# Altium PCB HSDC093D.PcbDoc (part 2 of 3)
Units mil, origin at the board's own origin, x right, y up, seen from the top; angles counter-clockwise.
Board outline 4360 x 2202.42 mil, 6 copper layers (Top Layer, GND1, VCC1, VCC2, GND2, Bottom Layer), stack 84.434 mil thick; 280 components, 182 nets, 800 pads, 401 vias.
Unrouted connection lines stored in the file: 5.
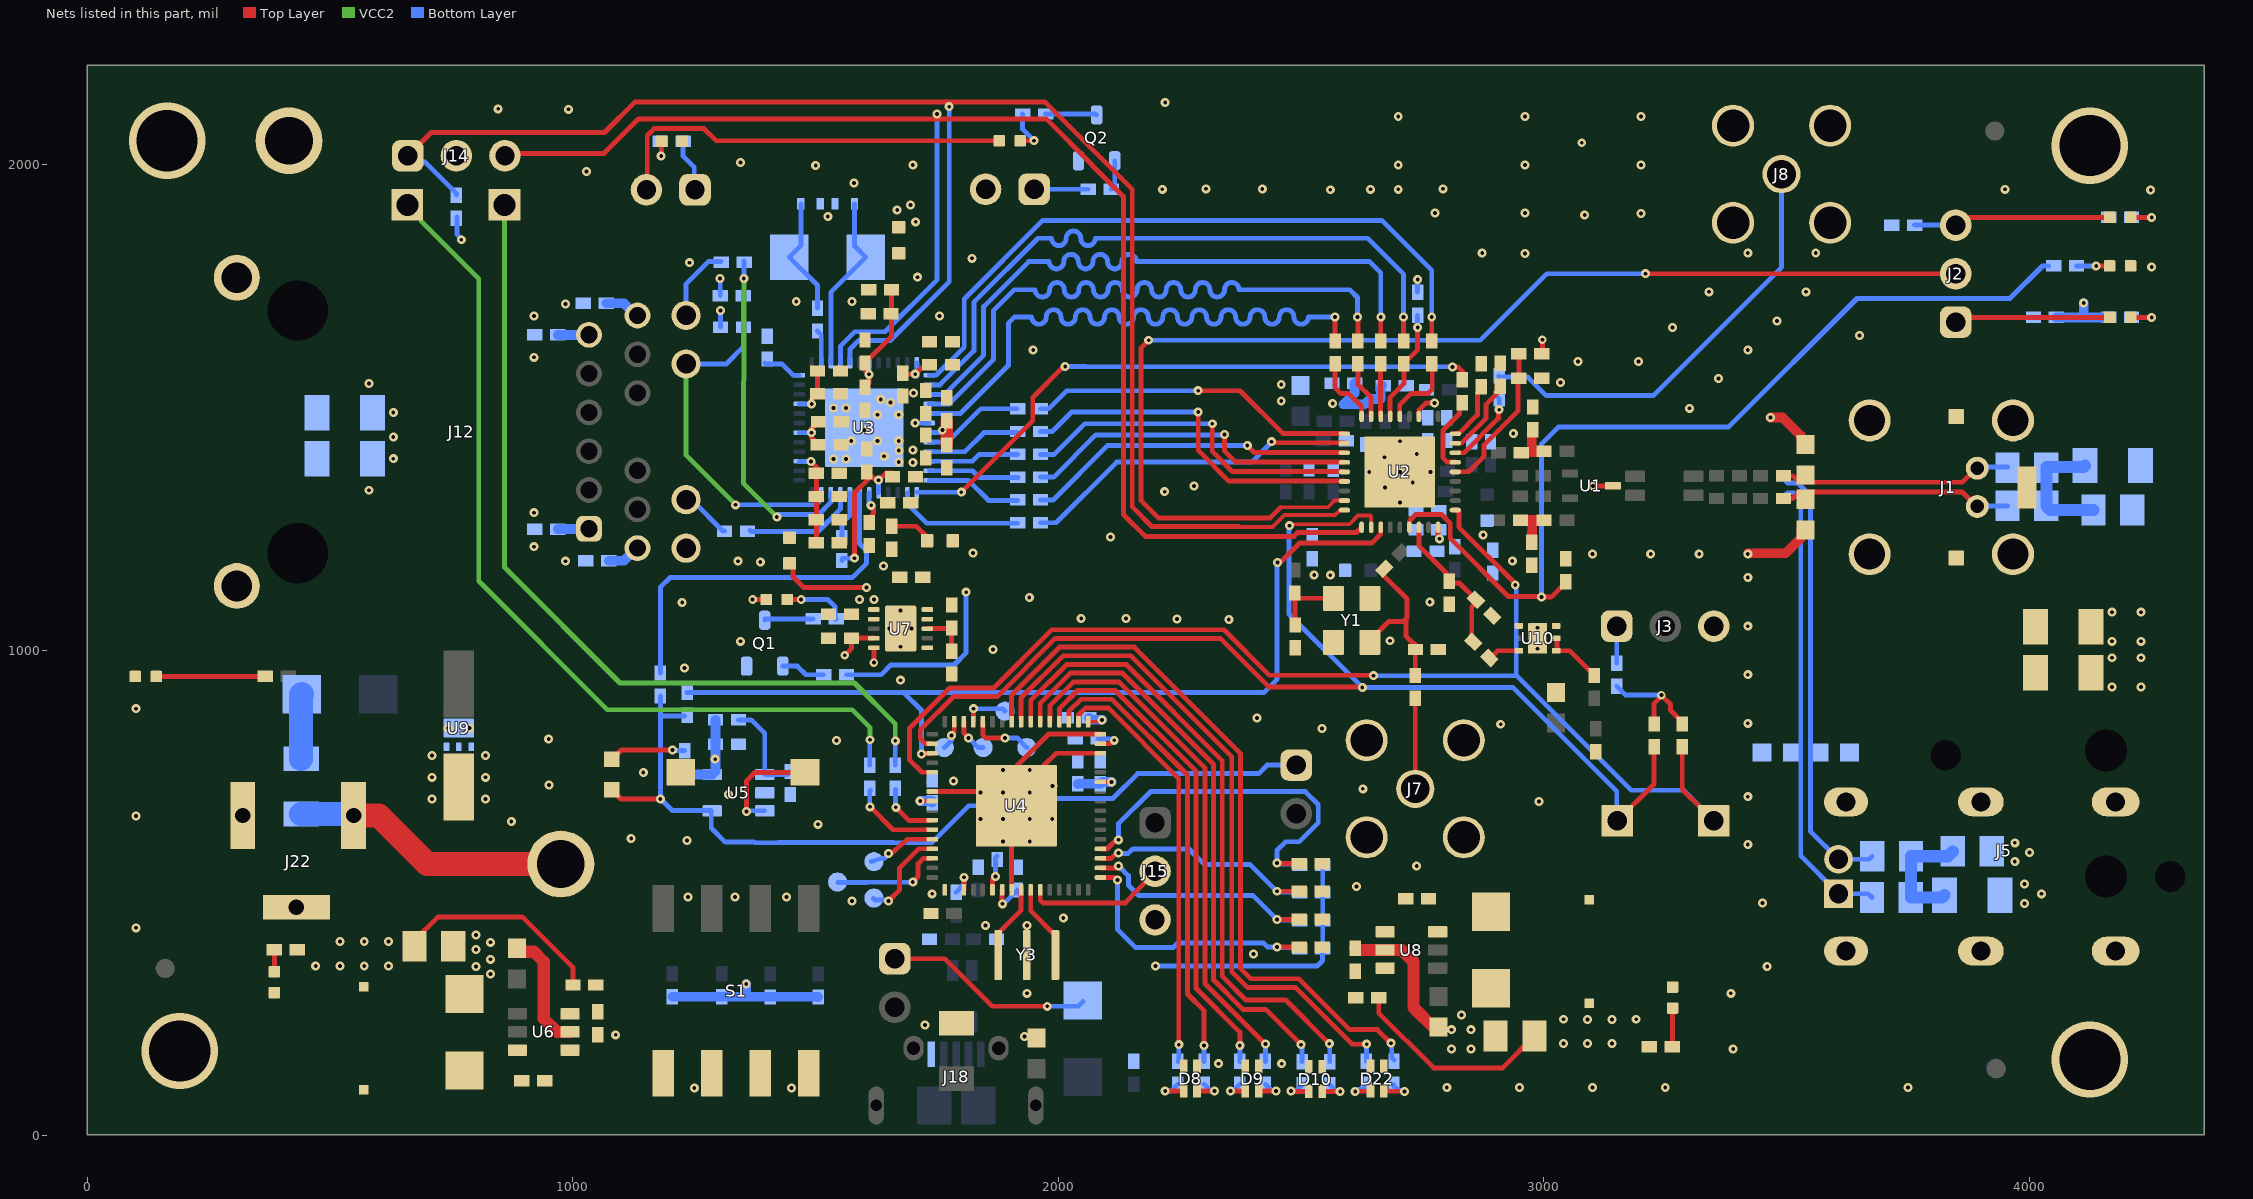
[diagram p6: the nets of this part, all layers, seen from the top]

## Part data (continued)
L1: library part CMP-0090833-1, "100μH @ 100kHz 2 Line Common Mode Choke Surface Mount 100mA DCR 3.12Ω", Manufacturer=Murata, Mouser Part Number=81-DLW32MH101XT2L, Operating Temperature Range="-40°C to +125°C", Test Frequency=100kHz, Tolerance_%=-25/+50%
L2: library part CMP-0003348-2, "Ferrite Bead, 1000 ohm @ 100 MHz, 0.6 A, 0603", Manufacturer=MuRata, Supplier Part Number 1=490-5215-1-ND, Value1="0.35 ohm", Value2=0.6A, ValueDisplayed="1000 ohm"
L3 L4 L5 L6 L7: library part CMP-0089848-1, "600 Ohms @ 100MHz 1 Power Line Ferrite Bead 0603 (1608 Metric) 1.3A 150mOhm", Digikey Part Number=490-13259-1-ND, Impedance At Frequency="600Ω @ 100MHz", Manufacturer=Murata, Mouser Part Number=81-BLM18KG601SH1D, Operating Temperature Range="-55°C to +125°C", Test Frequency=100MHz, Tolerance_%=25%
L8: library part CMP-0013079-2, "Coupled inductor,  A, 0.3 ohm, SMD", Manufacturer="Wurth Elektronik", Supplier Part Number 1=732-1469-1-ND
L9 L10: library part CMP-0064420-2, "Inductor, Shielded Drum Core, Ferrite, 15 uH, 1.15 A, 0.07 ohm, SMD", Manufacturer="Wurth Elektronik", Supplier Part Number 1=732-1045-1-ND, Value1="0.07 ohm", Value2=1.15A, ValueDisplayed=15uH
Logo1: library part CMP-0074844-1
Logo2: library part CMP-0074847-1, "FCC_disclaimer"
Logo3: library part CMP-0074838-1, "Texas Instrument Corporate Signature"
Logo4: library part CMP-0074769-1
Q1 Q2: library part CMP-0000376-2, "Transistor, NPN, 45 V, 0.1 A, SOT-23", Manufacturer="ON Semiconductor", Supplier Part Number 1=BC847CLT1GOSCT-ND, Value1="0.1 A", Value2=800
R1 R5 R16 R33 R95: library part CMP-0026237-2, "RES, 2.49 k, 1%, 0.063 W, AEC-Q200 Grade 0, 0402", Manufacturer=Vishay-Dale, Power_W=63mW, Supplier Part Number 1=541-2.49KLCT-ND, TempCo="100 ppm/C", Tolerance_%=1%, Value2=0.063W, Value_Code=2k49, ValueDisplayed=2.49k
R2 R13: library part CMP-0026210-2, "RES, 26.7, 1%, 0.063 W, AEC-Q200 Grade 0, 0402", Manufacturer=Vishay-Dale, Power_W=63mW, Supplier Part Number 1=541-26.7LCT-ND, TempCo="100 ppm/C", Tolerance_%=1%, Value2=0.063W, Value_Code=26R7, ValueDisplayed=26.7
R3 R7 R12 R20 R30 R61 R62 R65 R66 R67 R69 R101 R102: library part CMP-0026890-5, "RES, 2.2 k, 5%, 0.063 W, AEC-Q200 Grade 0, 0402", Manufacturer=Vishay-Dale, Power_W=63mW, Supplier Part Number 1=541-2.2KJCT-ND, TempCo="200 ppm/C", Tolerance_%=5%, Value2=0.063W, Value_Code=2k20, ValueDisplayed=2.2k
R4 R6 R8 R9 R10 R11 R17 R19 R22 R38 R56 R58 R59 R90 R91 R92 R93 R96 R98 R100: library part CMP-0081856-1, "RES, 0, 0%, 0.2 W, AEC-Q200 Grade 0, 0402", Manufacturer=Vishay-Dale, Power_W=200mW, Supplier Part Number 1=541-0.0YBTR-ND, Tolerance_%=0%, Value2=0.2W, Value_Code=0
R14 R15 R23 R24: library part CMP-0021848-2, "RES, 1.00 k, 1%, 0.25 W, 0805", Manufacturer=Panasonic, Power_W=250mW, Supplier Part Number 1=P16058CT-ND, TempCo="100 ppm/C", Tolerance_%=1%, Value2=0.25W, Value_Code=1k00, ValueDisplayed=1.00k
R18 R25: library part CMP-0020834-3, "RES, 100 k, 1%, 0.125 W, AEC-Q200 Grade 0, 0805", Manufacturer=Vishay-Dale, PartNumber=CRCW0805100KFKEA, Power_W=125mW, Supplier Part Number 1=541-100KCCT-ND, TempCo="100 ppm/C", Tolerance_%=1%, Value2=0.125W, Value_Code=100k
R21 R35: library part CMP-0018610-3, "RES, 1.0 M, 5%, 0.25 W, AEC-Q200 Grade 0, 1206", Manufacturer=Vishay-Dale, Power_W=250mW, Supplier Part Number 1=541-1.0MECT-ND, TempCo="200 ppm/C", Tolerance_%=5%, Value2=0.25W, Value_Code=1M00, ValueDisplayed=1.0M
R26 R31 R103 R104: library part CMP-0026992-3, "RES, 0, 5%, 0.1 W, AEC-Q200 Grade 0, 0402", Manufacturer=Panasonic, Power_W=100mW, Supplier Part Number 1=P0.0JCT-ND, TempCo="600 ppm/C", Tolerance_%=5%, Value2=0.1W, Value_Code=0000, ValueDisplayed=0
R27 R32 R34 R39 R40 R41 R42 R43 R44 R55 R72 R99: library part CMP-0026736-1, "RES, 470, 1%, 0.063 W, 0402", Manufacturer="Yageo America", Power_W=63mW, Supplier Part Number 1=311-470LRCT-ND, TempCo="100 ppm/C", Tolerance_%=1%, Value2=0.063W, Value_Code=470R, ValueDisplayed=470
R28: library part CMP-0026071-3, "RES, 1.00 k, 1%, 0.063 W, AEC-Q200 Grade 0, 0402", Manufacturer=Vishay-Dale, Power_W=63mW, Supplier Part Number 1=541-1.00KLCT-ND, TempCo="100 ppm/C", Tolerance_%=1%, Value2=0.063W, Value_Code=1k00, ValueDisplayed=1.00k
R29 R48 R49 R50 R51 R86 R87 R88 R89: library part CMP-0065360-1, "RES, 10.0 k, .1%, .0625 W, 0402", Manufacturer="Yageo America", Power_W=62.5mW, Supplier Part Number 1=YAG1346CT-ND, TempCo="25 ppm/C", Tolerance_%=0.1%, Value1=.1%, Value2=.0625W, Value_Code=10k0, ValueDisplayed=10.0k
R36: library part CMP-0025975-3, "RES, 11.0 k, 1%, 0.063 W, AEC-Q200 Grade 0, 0402", Manufacturer=Vishay-Dale, Power_W=63mW, Supplier Part Number 1=541-11.0KLCT-ND, TempCo="100 ppm/C", Tolerance_%=1%, Value2=0.063W, Value_Code=11k0, ValueDisplayed=11.0k
R37 R45: library part CMP-0026681-1, "RES, 2.20 k, 1%, 0.1 W, 0402", Manufacturer=Panasonic, Power_W=100mW, Supplier Part Number 1=P2.20KLCT-ND, TempCo="100 ppm/C", Tolerance_%=1%, Value2=0.1W, Value_Code=2k20, ValueDisplayed=2.20k
R46 R47: library part CMP-0026997-2, "RES, 22, 5%, 0.1 W, AEC-Q200 Grade 0, 0402", Manufacturer=Panasonic, Power_W=100mW, Supplier Part Number 1=P22JCT-ND, TempCo="200 ppm/C", Tolerance_%=5%, Value2=0.1W, Value_Code=22R0, ValueDisplayed=22
R52: library part CMP-0026085-3, "RES, 1.40 k, 1%, 0.063 W, AEC-Q200 Grade 0, 0402", Manufacturer=Vishay-Dale, Power_W=63mW, Supplier Part Number 1=541-1.40KLCT-ND, TempCo="100 ppm/C", Tolerance_%=1%, Value2=0.063W, Value_Code=1k40, ValueDisplayed=1.40k
R53: library part CMP-0085900-1, "RES, 1.00 M, 1%, 0.1 W, AEC-Q200 Grade 0, 0603", Manufacturer="Stackpole Electronics Inc", Power_W=100mW, TempCo="100 ppm/C", Tolerance_%=1%, Value2=0.1W, Value_Code=1M00, ValueDisplayed=1.00M
R54 R57: library part CMP-0026660-1, "RES, 1.00 M, 1%, 0.1 W, 0402", Manufacturer=Panasonic, Power_W=100mW, Supplier Part Number 1=P1.00MLCT-ND, TempCo="100 ppm/C", Tolerance_%=1%, Value2=0.1W, Value_Code=1M00, ValueDisplayed=1.00M
R60: library part CMP-0026334-2, "RES, 3.40 k, 1%, 0.063 W, AEC-Q200 Grade 0, 0402", Manufacturer=Vishay-Dale, Power_W=63mW, Supplier Part Number 1=541-3.40KLCT-ND, TempCo="100 ppm/C", Tolerance_%=1%, Value2=0.063W, Value_Code=3k40, ValueDisplayed=3.40k
R63 R71: library part CMP-0026072-3, "RES, 1.02 k, 1%, 0.063 W, AEC-Q200 Grade 0, 0402", Manufacturer=Vishay-Dale, Power_W=63mW, Supplier Part Number 1=541-1.02KLCT-ND, TempCo="100 ppm/C", Tolerance_%=1%, Value2=0.063W, Value_Code=1k02, ValueDisplayed=1.02k
R64: library part CMP-0026082-3, "RES, 1.30 k, 1%, 0.063 W, AEC-Q200 Grade 0, 0402", Manufacturer=Vishay-Dale, Power_W=63mW, Supplier Part Number 1=541-1.30KLCT-ND, TempCo="100 ppm/C", Tolerance_%=1%, Value2=0.063W, Value_Code=1k30, ValueDisplayed=1.30k
R68: library part CMP-0026409-2, "RES, 4.42 k, 1%, 0.063 W, AEC-Q200 Grade 0, 0402", Manufacturer=Vishay-Dale, Power_W=63mW, Supplier Part Number 1=541-4.42KLCT-ND, TempCo="100 ppm/C", Tolerance_%=1%, Value2=0.063W, Value_Code=4k42, ValueDisplayed=4.42k
R70: library part CMP-0026233-2, "RES, 2.26 k, 1%, 0.063 W, AEC-Q200 Grade 0, 0402", Manufacturer=Vishay-Dale, Power_W=63mW, Supplier Part Number 1=541-2.26KLCT-ND, TempCo="100 ppm/C", Tolerance_%=1%, Value2=0.063W, Value_Code=2k26, ValueDisplayed=2.26k
R73: library part CMP-0026879-3, "RES, 22 k, 5%, 0.063 W, AEC-Q200 Grade 0, 0402", Manufacturer=Vishay-Dale, Power_W=63mW, Supplier Part Number 1=541-22KJCT-ND, TempCo="200 ppm/C", Tolerance_%=5%, Value2=0.063W, Value_Code=22k0, ValueDisplayed=22k
R74 R75 R76 R77 R78 R79 R80 R81 R82 R83 R84 R85: library part CMP-0026880-3, "RES, 22, 5%, 0.063 W, AEC-Q200 Grade 0, 0402", Manufacturer=Vishay-Dale, Power_W=63mW, Supplier Part Number 1=541-22JCT-ND, TempCo="200 ppm/C", Tolerance_%=5%, Value2=0.063W, Value_Code=22R0, ValueDisplayed=22
R94: library part CMP-0026468-2, "RES, 5.76 k, 1%, 0.063 W, AEC-Q200 Grade 0, 0402", Manufacturer=Vishay-Dale, Power_W=63mW, Supplier Part Number 1=541-5.76KLCT-ND, TempCo="100 ppm/C", Tolerance_%=1%, Value2=0.063W, Value_Code=5k76, ValueDisplayed=5.76k
R97: library part CMP-0025951-3, "RES, 100, 1%, 0.063 W, AEC-Q200 Grade 0, 0402", Manufacturer=Vishay-Dale, Power_W=63mW, Supplier Part Number 1=541-100LCT-ND, TempCo="100 ppm/C", Tolerance_%=1%, Value2=0.063W, Value_Code=100R, ValueDisplayed=100
S1: library part CMP-0002176-2, "Switch, SPST 4 Pos, Top Actuated, SMT", CurrentRating_mA=100A, Manufacturer="CTS Electrocomponents", Supplier Part Number 1=CT2194LPST-ND
S2: library part CMP-0002170-2, "Switch, Normally open, 2.3N force, 200k operations, SMD", CurrentRating_mA=1.001kA, Manufacturer="C&K Components"
TP1 TP2 TP3 TP4 TP5 TP6 TP7: library part CMP-0003825-1, "1mm Test Point, SMT", Manufacturer=Any
TP8 TP9: library part CMP-0055113-1, "Terminal, Turret, TH, Double", Manufacturer=Keystone, Supplier Part Number 1=36-1502-2-ND
U1: library part CMP-0073595-1, "Automotive Dual-Channel High-Speed ESD Protection Device, DCK0003A (SOT-SC70-3)", Alternate Manufacturer="Texas Instruments"
U2: library part CMP-0085268-1, "Low Power Auto PHY 1000BASE-T1 Automotive Ethernet Physical Layer Transceiver, RND0036A (VQFNP-36)", Alternate Manufacturer="Texas Instruments", Alternate PartNumber=DP83TG720SWRNDTQ1
U3: library part CMP-0076013-2, "Extended Temperature Gigabit Ethernet PHY with SGMII, RGZ0048B (VQFN-48)", Alternate Manufacturer="Texas Instruments", Alternate PartNumber=DP83867ERGZT
U4: library part CMP-0039269-4, "16-Bit Ultra-Low-Power Microcontroller, 128KB Flash, 8KB RAM, USB, 12Bit ADC, 2 USCIs, 32Bit HW MPY, RGC0064B (VQFN-64)", Alternate Manufacturer="Texas Instruments", Alternate PartNumber=MSP430F5528IRGCR, Frequency(MHz)=25, Operating Temperature Range="-40 to 85 C", Rating=Catalog, Temp Sensor=Yes
U5: library part CMP-0074267-1, "Nanopower Supervisory Circuits for Automotive, DBV0005A (SOT-23-5)", Alternate Manufacturer="Texas Instruments"
U6 U8: library part CMP-0076377-2, "SIMPLE SWITCHER(R) 4.5V to 42V, 0.6A Step-Down DC/DC Switching Regulator in SOT-23 Package, DDC0006A (SOT-23-T-6)", Alternate Manufacturer="Texas Instruments", Alternate PartNumber=LMR14206XMKE/NOPB
U7: library part CMP-0036362-5, "Single Output LDO, 500mA, Adj. (0.8 to 3.6V), Programmable Soft-Start, DRC0010J (VSON-10)", Manufacturer="Texas Instruments", Operating Temperature Range="-40 to 125 C", Power Good=TRUE, Rating=Catalog
U9: library part CMP-0013424-7, "33-V Precision Surge Protection Clamp, DRV0006A (WSON-6)", Alternate Manufacturer="Texas Instruments", Alternate PartNumber=TVS3300DRVT
U10: library part CMP-0860463-1, "Automotive 150-mA high-voltage ultra-low-IQ low-dropout (LDO) linear regulator, DRV0006A (WSON-6)", Alternate Manufacturer="Texas Instruments", Operating Temperature Range="-40 to 150 C", Rating=Automotive
Y1: library part CMP-0004682-5, "Crystal, 25 MHz, 12pF, AEC-Q200 Grade 1, SMD", Frequency_Fixed=25MHz, Frequency Stability="50 ppm", Load Capacitance="12 pF", Manufacturer="Abracon Corporation"
Y2: library part CMP-0004665-3, "Crystal, 25 MHz,  SMD", Frequency_Fixed=25MHz, Frequency Stability=+/-30ppm, Manufacturer=NDK, Supplier Part Number 1=644-1274-1-ND
Y3: library part CMP-0006148-5, "Resonator, 4 MHz, 1000 ppm, 39 pF, SMD", Frequency_Fixed=4MHz, Frequency Stability="800 ppm", Frequency Tolerance="1000 ppm", Load Capacitance="39 pF", Manufacturer=MuRata, Supplier Part Number 1=490-7861-1-ND

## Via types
v1: diameter 18.5, hole 7.87, Top Layer to Bottom Layer, tented both sides, 357 vias
v2: diameter 19.68, hole 7.87, Top Layer to Bottom Layer, 25 vias
v3: diameter 17.72, hole 7.87, Top Layer to Bottom Layer, tented both sides, 8 vias
v4: diameter 19.68, hole 7.87, Top Layer to Bottom Layer, tented both sides, 7 vias
v5: diameter 157.48, hole 125.98, Top Layer to Bottom Layer, 4 vias

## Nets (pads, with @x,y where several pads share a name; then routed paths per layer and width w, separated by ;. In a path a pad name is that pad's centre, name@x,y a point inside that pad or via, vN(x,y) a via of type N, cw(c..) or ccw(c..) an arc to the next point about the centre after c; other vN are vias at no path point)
720_RX_CLK: R79.2 U2.27 | length 139.3
  Top Layer w10: R79.2@2570,1590 2570,1541 2581.87,1529.13 2597.16,1529.13 2597.29,1529 2598,1529 2624.32,1502.68 U2.27@2624.32,1482.58
720_RX_CTRL: R78.2 U2.15 | length 158.5
  Top Layer w10: U2.15@2817.24,1388.09 2800.91,1388.09 2792,1397 2792,1453.13 2803.23,1464.36 2826.24,1487.37 2826.24,1504.24 R78.2@2832,1510
720_RX_D0: R77.2 U2.26 | length 117.6
  Top Layer w10: R77.2@2617,1589 2617,1548 2644.01,1520.99 U2.26@2644.01,1482.58
720_RX_D1: R76.2 U2.25 | length 106.5
  Top Layer w10: U2.25@2663.69,1482.58 2663.69,1588.69 R76.2@2664,1589
720_RX_D2: R75.2 R95.1 U2.24 | length 230.3
  Top Layer w10: U2.24@2683.38,1482.58 2683.38,1521.38 2712,1550 R75.2@2712,1589 ; R75.2@2711,1590.38 2740,1619.38 v1(2740,1665)
  Bottom Layer w10: v1(2740,1665) R95.1@2740,1690.38
720_RX_D3: R74.2 U2.23 | length 155.6
  Top Layer w10: U2.23@2703.06,1482.58 2703.06,1506.06 2726,1529 2761,1529 2770,1538 R74.2@2770,1590
720_TX_CLK: R81.1 U2.28 | length 677.5
  Top Layer w10: v1(2288,1535) 2292,1535 2374,1535 2462,1447 U2.28@2589,1447
  Bottom Layer w10: R81.1@1963.24,1498 1980,1498 2017,1535 2284,1535 v1(2288,1535)
720_TX_CTRL: R80.1 U2.29 | length 698.2
  Top Layer w10: v1@2441,1430 v1(2439,1430) 2441,1428 2473,1428 U2.29@2588.89,1427.46
  Bottom Layer w10: R80.1@1963.24,1263 1995,1263 2119.87,1387.87 2397.87,1387.87 2439,1429 v1(2439,1430)
720_TX_D0: R82.1 U2.33 | length 747.4
  Top Layer w10: v1(2288,1491) 2288,1412 2351.28,1348.72 U2.33@2588.89,1348.72
  Bottom Layer w10: R82.1@1963.24,1451 1987,1451 2027,1491 v1(2288,1491)
720_TX_D1: R83.1 U2.32 | length 726
  Top Layer w10: v1(2317,1467) 2317,1410 2358.59,1368.41 U2.32@2588.89,1368.41
  Bottom Layer w10: R83.1@1963.24,1404 1991,1404 2054,1467 v1(2317,1467)
720_TX_D2: R84.1 U2.31 | length 707.3
  Top Layer w10: v1(2342,1445) 2342,1411 2365,1388 2365.09,1388.09 U2.31@2588.89,1388.09
  Bottom Layer w10: R84.1@1963.24,1357 1990,1357 2077,1444 v1@2344,1444
720_TX_D3: R85.1 U2.30 | length 677.9
  Top Layer w10: v1(2389,1422) 2403.22,1407.78 U2.30@2588.89,1407.78
  Bottom Layer w10: R85.1@1963.24,1310 1989,1310 2101,1422 v1(2389,1422)
867_RX_CLK: R81.2 U3.32 | length 209.5
  Bottom Layer w10: U3.32@1734.02,1429.09 1771.09,1429.09 1840,1498 R81.2@1915,1498
867_RX_CTRL: R80.2 U3.38 | length 266
  Bottom Layer w10: U3.38@1689,1324.5 1689,1302.06 1729.06,1262 R80.2@1916,1262
867_RX_D0: R82.2 U3.33 | length 198.4
  Bottom Layer w10: U3.33@1734.02,1409.41 1807.41,1409.41 1847,1449 R82.2@1916,1449
867_RX_D1: R83.2 U3.34 | length 187.9
  Bottom Layer w10: U3.34@1734.02,1389.72 1822.72,1389.72 1837,1404 R83.2@1916,1404
867_RX_D2: R84.2 U3.35 | length 188.8
  Bottom Layer w10: U3.35@1734.02,1370.04 1822.96,1370.04 1837,1356 R84.2@1917,1356
867_RX_D3: R85.2 U3.36 | length 199.1
  Bottom Layer w10: U3.36@1734.02,1350.35 1814.65,1350.35 1856,1309 R85.2@1916,1309
867_TX_CLK: R79.1 U3.29 | length 1345
  Top Layer w10: R79.1@2570,1637.62 v1(2570,1687)
  Bottom Layer w10: U3.29@1734.02,1488.15 1798.15,1488.15 1897,1587 1897,1674 1910,1687 1915,1687 1945,1687 ccw(c1960,1687) 1975,1687 cw(c1990,1687) 2005,1687 ccw(c2020,1687) 2035,1687 cw(c2050,1687) 2065,1687 ccw(c2080,1687) 2095,1687 cw(c2110,1687) 2125,1687 ccw(c2140,1687) 2155,1687 cw(c2170,1687) 2185,1687 ccw(c2200,1687) 2215,1687 cw(c2230,1687) 2245,1687 ccw(c2260,1687) 2275,1687 cw(c2290,1687) 2305,1687 ccw(c2320,1687) 2335,1687 cw(c2350,1687) 2365,1687 ccw(c2380,1687) 2395,1687 cw(c2410,1687) 2425,1687 ccw(c2440,1687) 2455,1687 cw(c2470,1687) 2485,1687 ccw(c2500,1687) 2515,1687 2529,1687 v1(2570,1687) v1@2571,1687
867_TX_CTRL: R78.1 U3.37 | length 1273.1
  Top Layer w10: v1(1800,1326) 1947,1473 1947,1521 v1@2010,1584 ; v1(2812,1584) 2823,1584 2832,1575 R78.1@2832,1558.62
  Bottom Layer w10: U3.37@1709,1326 v1(1800,1326) ; v1(2014,1585) 2055,1585 ; 2056,1584.87 v1(2812,1584)
867_TX_D0: R77.1 U3.28 | length 1374.7
  Top Layer w10: v1(2616,1687) 2616,1686 2617,1685 R77.1@2617,1637.62
  Bottom Layer w10: U3.28@1734.02,1507.83 1774.83,1507.83 1866,1599 1866,1700 1909,1743 1922,1743 1952,1743 ccw(c1967,1743) 1982,1743 cw(c1997,1743) 2012,1743 ccw(c2027,1743) 2042,1743 cw(c2057,1743) 2072,1743 ccw(c2087,1743) 2102,1743 cw(c2117,1743) 2132,1743 ccw(c2147,1743) 2162,1743 cw(c2177,1743) 2192,1743 ccw(c2207,1743) 2222,1743 cw(c2237,1743) 2252,1743 ccw(c2267,1743) 2282,1743 cw(c2297,1743) 2312,1743 ccw(c2327,1743) 2342,1743 cw(c2357,1743) 2372,1743 2381,1743 2600,1743 2616,1727 v1(2616,1687)
867_TX_D1: R76.1 U3.27 | length 1353.3
  Top Layer w10: R76.1@2664,1637.62 v1@2664,1686
  Bottom Layer w10: U3.27@1734.54,1527 1765,1527 1846,1608 1846,1708.28 1938.72,1801 1951,1801 1981,1801 ccw(c1996,1801) 2011,1801 cw(c2026,1801) 2041,1801 ccw(c2056,1801) 2071,1801 cw(c2086,1801) 2101,1801 ccw(c2116,1801) 2131,1801 cw(c2146,1801) 2161,1801 2173,1801 2641,1801 2664,1778 v1(2664,1687)
867_TX_D2: R75.1 U3.26 | length 1377.9
  Top Layer w10: R75.1@2711,1637.62 v1@2711,1685
  Bottom Layer w10: U3.26@1734.22,1547 1756,1547 1826,1617 1826,1717 1958,1849 1986,1849 ccw(c2001,1849) 2016,1849 cw(c2031,1849) 2046,1849 ccw(c2061,1849) 2076,1849 2097,1849 2637,1849 2711,1775 v1(2711,1687)
867_TX_D3: R74.1 U3.25 | length 1409.2
  Top Layer w10: R74.1@2769,1641.62 v1(2769,1687)
  Bottom Layer w10: U3.25@1734.02,1566.89 1747.89,1566.89 1806,1625 1806,1724 1968,1886 2666,1886 2769,1783 v1(2769,1687)
83867_RESET_N: R56.2 U3.43 | length 772.8
  Bottom Layer w10: R56.2@1180,953.62 1180.28,1130.28 1200,1150 1560,1150 1575,1150 1605,1180 1605,1205 1590.32,1219.69 U3.43@1590.32,1324.76
+1V0: C25.1 J21.1 L4.1 R62.2 | length 111.4
  Bottom Layer w10: J21.1@1950,1950 R62.2@2061.38,1950
  other v1: 2560,1155 2526.88,1155.76
+1V0_867: C45.1 C46.1 C47.1 C48.1 C49.1 C50.1 C51.1 C52.1 C53.1 C54.1 L5.2 U3.6 U3.24 U3.31 U3.42 | length 414.5
  Top Layer w10: C53.1@1504.96,1424.13 1491.49,1437.6 v1(1491.49,1448.51) 1491.49,1457.2 C54.1@1505.67,1471.38 ; C48.1@1608.1,1271.34 1618.77,1282.01 v1@1618.77,1299.04 ; C45.1@1656.38,1255.75 1707.25,1255.75 1722.28,1240.72 1723,1240.72 1729,1234.72 1729,1228 L5.2@1729,1227 ; C52.1@1680,1569.39 1684.39,1565 1688.39,1569 v1(1705,1569) 1707.89,1569 1706.44,1570.44 1722.58,1586.58 C51.1@1733.46,1586.58
  Top Layer w25: C49.1@1770,1423.39 C50.1@1770,1473.41
  Bottom Layer w10: U3.6@1466.14,1448.51 v1(1491.49,1448.51) ; U3.42@1610,1324.76 1610,1299.04 v1(1614.38,1299.04) ; v1(1705,1569) 1705,1567.95 1707.95,1565 1708.43,1565.48 U3.24@1708.43,1592.48 ; U3.31@1734.02,1448.78 1755.78,1448.78 v3(1761,1454)
+1V0_REG: C85.1 J21.2 L5.1 R61.2 R64.1 U7.9 U7.10 | length 390
  Bottom Layer w10: R61.2@1563.62,950 1635,950 1655,970 1785,970 1810,995 v1(1810,1120)
+2V5_867: C63.1 C64.1 C65.1 C66.1 C67.1 C68.1 L7.2 U3.3 U3.9 | length 295.3
  Top Layer w10: v1(1490.3,1389.46) 1501.38,1378.38 C66.1@1501.38,1365.24 C65.1@1501.38,1317.14 C63.1@1501.38,1269.37 C64.1@1501.38,1221.54 ; v1(1491.73,1507.57) 1491.73,1516.61 C68.1@1503.74,1528.62 C67.1@1503.74,1575.67
  Bottom Layer w10: U3.3@1466.14,1389.46 v1(1490.3,1389.46) ; U3.9@1466.14,1507.57 v1(1491.73,1507.57)
+2V5_REG: C87.1 C89.1 L7.1 L10.2 R70.2 R72.1 U7.1 U7.2 U7.5 | length 647.7
  Top Layer w10: L7.1@1446,1179.43 1453.37,1172.06 1453.37,1151.63 1475,1130 v1(1605,1130) ; U7.5@1619.88,1005.63 1619.88,975.12 v3(1620,975) ; R70.2@2659.91,284.16 2659.91,253.14 2772.78,140.26 2914.85,140.26 C89.1@2980.48,205.89
  other v1: 3040.12,190.37 3090.12,190.37 3140.12,190.37 3040.12,240.37 3090,240 3140,240 3190.12,240.37 1590,1105 1620,1105
+3V3: C11.1 C19.1 J20.1 L2.1 L3.1 R5.2 R7.2 R20.2 R29.2 R69.1 R95.2 R101.2 R102.1 | length 544.2
  Top Layer w10: v3@2994,1639 2995,1640 v3(2997,1640) ; v3@2995,1639 2997,1637 2997,1612.38 R29.2@2995.62,1611 ; R101.2@3228,847 3227,848 R101.2@3227,848.62 3227,890.91 3242,905.91 v3(3242,908) ; v3@3243,908 3243,907 3260.83,889.17 3260.83,876.73 3285,852.56 R102.1@3285,848.62
  Bottom Layer w10: R69.1@1227.04,2048.82 1227.04,2017.96 1250,1995 J20.1@1250,1955 ; R95.2@2739,1738 2740,1739 v1(2740,1764) ; R20.2@3150,926.38 3168.38,908 v3(3242,908)
  Bottom Layer w20: R5.2@4055.62,1686 4112,1686 ; v1(4112,1716) 4112,1686 ; R7.2@4163.25,1686 4112,1686
  other v1: 2875,1238 2459,1514 2459,1548
+3V3_867: C55.1 C56.1 C57.1 C58.1 C59.1 C60.1 C61.1 C62.1 L6.1 R37.1 U3.19 U3.30 U3.41 | length 581.6
  Top Layer w10: v1(1580,1190) 1580,1325 C57.1@1610,1355 ; C60.1@1601.58,1542.24 1610,1550.67 v1(1610,1568.79) 1601.58,1577.21 C59.1@1601.58,1592.29 1656.38,1647.09 C56.1@1656.38,1743.39 ; C57.1@1614.85,1359.85 1624.05,1350.66 v1(1629.69,1350.66) 1644.26,1365.24 C58.1@1658.35,1365.24 ; C61.1@1731.38,1481.38 C61.1@1731.38,1493.03
  Bottom Layer w10: R37.1@1554,1185.38 1555,1190 v1(1580,1190) ; v1(1610,1568.79) U3.19@1610,1592.48 ; U3.41@1629.69,1324.76 v1(1629.69,1350.66) ; v1(1705,1468.46) U3.30@1734.02,1468.46
+3V3_REG: C77.1 C78.1 C79.1 C80.1 C81.1 C83.1 C86.1 D13.2 D14.2 J20.2 L6.2 L9.2 R45.2 R48.2 R49.2 R50.2 R51.2 R55.2 R57.1 R60.2 R67.1 R86.2 R87.2 R88.2 R89.2 R94.2 U4.11 U4.15 U4.40 U5.5 U7.4 | length 2747.8
  Top Layer w8: v1(1715.24,690) 1720,690 1720.16,689.84 U4.40@1740.2,689.84 ; U4.11@2086.65,729.21 v1(2109.45,729.21)
  Top Layer w10: C83.1@673.48,390.61 673.48,402.53 722.28,451.32 895.68,451.32 999.96,347.05 R60.2@999.96,310.88 ; J20.2@1155,1955 1153,1957 1153,2060.7 1167.3,2075 1270,2075 1295,2050 D14.2@1878.35,2050 ; v3(1370,1105) D13.2@1398.35,1105 ; v3(1560,990) 1573.62,1003.62 C86.1@1573.62,1025 ; C86.1@1575.32,1025.32 U7.4@1619.88,1025.32 ; U4.15@2086.65,807.95 2107.95,807.95 v1(2115,815)
  Bottom Layer w10: R45.2@761,1893 761,1857.3 770,1848.3 v1(770,1846) ; v1(1303,1766) 1303.38,1765.62 R94.2@1303.38,1731 ; C77.1@2081.81,817.99 2112.01,817.99 v1(2115,815) ; v1(2200,350) 2533,350 2544,361 2544,383 2544.62,383.62 R86.2@2544.62,386 R87.2@2544.62,441.38 ; R89.2@2544.62,558 R88.2@2544.62,501 R88.2@2544.62,499.38 ; R87.2@2545,441 R87.2@2544.62,441.38 ; R88.2@2546,498 R88.2@2544.62,499.38 ; R87.2@2544.62,441.38 R87.2@2544.62,443 R88.2@2544.62,499.38
  Bottom Layer w20: R48.2@1204.33,286.84 R49.2@1306.11,286.84 1357,286.84 ; R55.2@1230,746.38 1231.37,744.49 U5.5@1286.94,744.49 1293.67,751.22 v1@1293.67,776 ; v1(1293,776) v1@1293.67,776 ; R57.1@1293.67,857.09 C81.1@1293.67,807.09 v1@1293.67,776 ; v1(1357,313) 1357,286.84 ; R51.2@1504.92,286.38 1504.46,286.84 1406.11,286.84 1357,286.84 ; v1(1715.24,690) 1740,690 C80.1@1740,686.38 ; C78.1@2040,725 2040.28,725.28 C79.1@2086.65,725.28 2090.59,729.21 v1(2109.45,729.21)
  other v1: 470.12,350.37 520.12,350.37 570.12,350.37 620.12,350.37 520.12,400.37 570.12,400.37 620.12,400.37 1706,1883 1668,1907 1695,1917.79
CLKOUT: R31.1 U2.16 | length 153.1
  Top Layer w10: U2.16@2824.3,1407.28 2835.61,1407.28 2906.37,1478.04 2906.37,1492.37 v1@2907,1493
  Bottom Layer w10: R31.1@2905.86,1520.63 R31.1@2908,1518.38 v1@2908,1495
  other v1: 2908,1496
CON1_N: D1.1 J1.1 R6.2 R15.2 | length 481
  Top Layer w10: R6.2@3493.62,1360 3512.26,1360 D1.1@3523,1349.26 ; D1.1@3524.98,1346.94 3539,1346.92 3861.84,1346.44 3893.28,1377.88 J1.1@3892.68,1375.46
  Bottom Layer w10: J1.1@3892.68,1375.46 3895.1,1377.88 R15.2@3954.99,1377.88
CON1_P: D5.2 J1.2 R10.2 R14.2 | length 478.6
  Top Layer w10: R10.2@3493.62,1313 3512.31,1313 D5.2@3523,1323.69 ; D5.2@3524.98,1326.04 3539,1326.06 3861.63,1326.44 3888.93,1299.14 3893.28,1299.14 J1.2@3892.68,1296.72
  Bottom Layer w10: J1.2@3892.68,1296.72 3893.65,1297.69 R14.2@3954.99,1297.69
CON2_N: D6.2 J5.2 R8.2 R24.2 | length 913.4
  Bottom Layer w10: R8.2@3493.62,1360 3498.62,1355 3498.62,1348.38 3502,1345 3523.28,1345 3549,1319.28 3549,627.72 J5.2@3606.89,569.83 ; J5.2@3615.17,569.83 3670.14,569.83 R24.2@3676.4,576.09
CON2_P: D7.2 J5.1 R9.2 R23.2 | length 964.8
  Bottom Layer w10: R9.2@3493.62,1313 3498.62,1318 3498.62,1321.62 3502,1325 3515,1325 3529,1311 3529,576.85 J5.1@3606.89,498.96 3668.03,498.96 R23.2@3675.9,491.09
DP83TG720_RESET_N: R58.2 U2.3 U4.35 | length 1877.8
  Top Layer w10: v1@1717.01,787.99 1739.92,787.99 U4.35@1740.2,788.27 ; v1@2458.57,1183 2496.57,1221 2645,1221 2663.87,1239.87 U2.3@2663.87,1246.84
  Bottom Layer w10: R58.2@1235,913.62 2423.62,913.62 2450,940 v1@2450,1179 ; 1669,913 1681.72,913 1718,876.72 v1(1718,787)
  other v1: 2451,1181
GND: C1.1 C6.2 C7.2 C8.1 C9.2 C10.2 C11.2 C12.2 C13.2 C14.2 C15.2 C16.2 C17.2 C18.2 C19.2 C20.2 C21.2 C22.2 C23.2 C24.2 C25.2 C26.2 C27.2 C28.2 C29.2 C30.2 C31.2 C32.2 C33.2 C34.2 C35.2 C36.1 C37.1 C38.1 C39.2 C41.1 C42.1 C43.2 C44.1 C45.2 C46.2 C47.2 C48.2 C49.2 C50.2 C51.2 C52.2 C53.2 C54.2 C55.2 C56.2 C57.2 C58.2 C59.2 C60.2 C61.2 C62.2 C63.2 C64.2 C65.2 C66.2 C67.2 C68.2 C69.2 C70.1 C71.1 C72.1 C73.2 C74.1 C75.1 C76.2 C77.2 C78.2 C79.2 C80.2 C81.2 C83.2 C85.2 C86.2 C87.2 C89.2 C91.2 D1.2 D2.1 D5.1 D6.1 D7.1 D8.3 D8.4 D9.3 D9.4 D10.3 D10.4 D15.2 D16.1 D17.1 D18.2 D19.1 D21.1 D22.3 D22.4 J3.3 J7.2 J7.3 J7.4 J7.5 J8.2 J8.3 J8.4 J8.5 J12.13 J14.2 J15.3 J18.5 J22.2 J22.3 Q1.2 Q2.2 R1.2 R12.2 R16.2 R18.1 R21.2 R25.1 R30.2 R33.1 R35.2 R36.2 R53.2 R54.2 R59.1 R63.1 R68.1 R71.1 R90.2 R91.2 R92.2 R93.2 R103.2 R104.2 S1.1 S1.2 S1.3 S1.4 S2.2 TP9.1 U1.3 U2.37 U3.49@1600.16,1458.62 U4.14 U4.16 U4.39 U4.49 U4.56 U4.65 U5.2 U6.2 U7.6 U7.11 U8.2 U9.1 U9.2 U9.3 U9.7@765,840 U10.3 U10.4 U10.7@2987,1025 Y1.2 Y1.4 Y3.2 | length 1552.2
  Top Layer w10: U4.39@1740.2,709.53 1843.53,709.53 U4.65@1844,710 ; U4.65@1884.53,709.53 U4.65@1885,710 ; U4.65@1903,607 1903.58,606.42 U4.56@1903.58,506.77 ; U4.65@1903.58,673.58 U4.65@1910,680 ; U4.65@1913,761 1979.64,827.64 U4.16@2086.65,827.64 ; U4.65@1969,762 1995.27,788.27 U4.14@2086.65,788.27 ; v1(3101,1339) U1.3@3142.17,1339
  Top Layer w12: C85.2@1673,1152 C85.2@1673.62,1151.38 ; C1.1@2975,1500 C1.1@2977.83,1502.83
  Top Layer w20: v1@3420,1200 3498,1200 3530,1232 D5.1@3530,1247.01 ; v1(3467,1480) 3492,1480 3530,1442 D1.2@3530,1432
  Top Layer w25: C35.2@891,388 891,379.51 891.2,379.31 919.69,379.31 940,359 940,241.55 967.4,214.14 U6.2@993.99,214.14 ; R71.1@2611.28,386.53 2614.83,382.98 2707.47,382.98 2731.28,359.16 2731.28,264.72 C39.2@2776,220
  Bottom Layer w10: R33.1@1304,1666 v1(1304,1700)
  Bottom Layer w20: C11.2@2610,1550 2610,1530 2587,1507 2631,1507 2642,1518 2664,1518 2664,1543 C9.2@2667,1546
  other v1: 1250,98.79 1450,98.79 2800,100 2950,100 3100,100 3250,100 3750,100 2330,148.79 2460,148.79 2810,178.79 2850,178.79 3390,178.79 1930,205 1088.12,208.37 2810,218.79 2850,218.79 1725,228.79 2830,248.79 1935,293.79 3385,293.79 830,333.79 800,348.79 3460,348.79 830,363.79 2402,375 800,383.79 830,398.79 800,413.79 100,428.79 1850,433.79 1935,433.79 2010,448.79 3990,478.79 3450,480 1575,484 1237,492 1334,492 1440,492 1740,498.79 4025,498.79 2614,514 3990,518.79 2738,556 3970,565 4000,583.79 3420,600 3970,603.79 1235,608.79 1120,612.79 1505,642 873,647.79 100,658.79 2990,688.79 710,693.79 820,693.79 3420,698.79 1320,703.79 2627,715 951,722.79 1784,731 710,738.79 820,738.79 1145,748.79 710,783.79 820,783.79 1543,814.79 950,817.79 2543,839 2911,848 3420,850 2409,861 100,880 4170,925 4230,925 1675,938.79 3420,950 1230,963.79 4170,985 4230,985 1865,1001.79 1345,1018.79 4170,1018.79 4230,1018.79 2683,1020 3420,1050 2351,1064 2244,1065 2047,1066 2139,1066 4170,1078.79 4230,1078.79 1225,1098.79 2765,1100 1940,1108.79 3420,1150 1640,1173.79 1386,1182 985,1183.79 1340,1183.79 2935,1184 3100,1198.79 3220,1198.79 3320,1198.79 3420,1198.79 1824,1201 920,1213.79 2107,1234 920,1283.79 2219,1327 580,1330 2673,1336 2279,1339 2730,1346 1700,1386.89 1671.22,1387.96 1536.81,1394.43 630,1395 1562.4,1394.53 2672,1398 2738,1405 1671.22,1412.19 1700,1413 630,1440 2937,1447 1600,1453.79 630,1490 1536.81,1499.4 3300,1498.79 1562.4,1499.75 2565,1509 1654,1511 1701.65,1530 580,1550 3034,1552 3360,1560 3070,1595 3195,1595 920,1603.79 1948,1618.79 3420,1618.79 3650,1648.79 3265,1665 3480,1678.79 920,1688.79 1755,1688.79 985,1713.79 1460,1718.79 1575,1718.79 3340,1738.79 3540,1738.79 1710,1768.79 4252,1789.79 1240,1798.79 1822,1807.79 2961,1818 2873,1819 3420,1818.79 3560,1818.79 1525,1893.79 3084,1896.79 3200,1900 2776,1901 2961,1901 2560,1949 4250,1948.79 2214,1950 2643,1950 2700,1950 3950,1950 2304,1951 2420,1950.79 2792,1951 1579,1962.79 1028,1986.79 1500,1998.79 1700,2000 2700,2000 2961,2000 3200,2000 1345,2004.79 3078,2045.79 2700,2100 2961,2100 3200,2100 991,2114.79 846,2115.79 2220,2128.79
  other v2: 1886.06,606.18 1940.79,606.18 1839.61,652.64 1886.06,652.64 1940.79,652.64 1987.24,652.64 1839.61,707.36 1886.06,707.36 1940.79,707.36 1988,721 1886.06,753.82 1940.79,753.82 743.35,840 786.65,840 2987,1003.35 1675,1007.6 1652.36,1045 1697.64,1045 2987,1046.65 1675,1082.4 2703.32,1304.83 2640.32,1367.83 2703.32,1367.83 2766.31,1367.83 2703.32,1430.82
  other v4: 1641,1400 1573.19,1431.65 1627.13,1431.65 1671.02,1431.65 1627.13,1485.59 1671.02,1485.59 1634,1517
  other v5: 4124.7,157.48 190,175 4124.7,2040 163.96,2050
GND720: C8.2 J1.S1 J1.S2 J1.S3 J1.S4 J1.S5 J1.S6 J1.S7 J5.S1 J5.S2 J5.S3 J5.S4 J5.S5 J5.S6 R21.1
GND867: C36.2 J12.S1 J12.S2 R35.1
INH: J6.1 R102.2 U2.10 U4.37 | length 2591.1
  Top Layer w10: U4.37@1733.39,749 1719,749 1693,775 1693,839.3 1776.46,922.76 1866.48,922.76 1986.32,1042.6 2341.11,1042.6 2434.71,949 v1@2645,949 ; U2.10@2817.24,1289.67 2820.33,1289.67 2825.02,1284.98 2825.02,1253.98 2941,1138 v1(2941,1135) ; R102.2@3285,801.38 3285,713 3303.26,694.74 3304.26,694.74 3347,652 J6.1@3352,652
  Bottom Layer w10: v1(2649,948) 2944,948 ; v1@2942,1135 2942,1134 2943,1133 2943,949 2944,948 ; J6.1@3350,650 3288,712 3180,712 2944,948
INT: J4.1 R101.1 U2.2 U4.34 | length 2536.6
  Top Layer w8: v1@2474,1260 2599.45,1260 2617.37,1277.92 2642.08,1277.92 2644.01,1275.99 U2.2@2644.01,1254.24
  Top Layer w10: U4.34@1740.2,807.95 1739.92,808.23 1726.03,808.23 1715.51,818.74 1715.51,836.53 1783.86,904.88 1873.88,904.88 1993.72,1024.72 2333.28,1024.72 2433,925 v1@2628,925 ; J4.1@3151,649 3227,725 3227,799 R101.1@3229,801
  Bottom Layer w10: v1@2475,1261 2475,1075 v1(2626,924) 2936,924 3150,710 3150,650 J4.1@3151,649
  other v1: 2476,1257
LED01: J12.15 R33.2 R94.1 U3.47 | length 766
  VCC2 w10: J12.15@1233,1590.12 1233,1402 v1(1335,1300)
  Bottom Layer w10: J12.15@1234,1590 1316,1590 1351.24,1625.24 R33.2@1351.24,1666 1351.24,1731.76 R94.1@1351,1732 ; v1(1335,1300) 1500.71,1300 1511.57,1310.87 U3.47@1511.57,1324.76
LED11: R34.1 U3.46 | length 701.8
  VCC2 w10: v1(1352,1766) 1351,1344 v1(1420,1275)
  Bottom Layer w10: v1(1352,1766) R34.1@1352,1802 ; v1(1420,1275) 1420,1280 1505.98,1280 1531.26,1305.28 U3.46@1531.26,1324.76
LED21: R32.2 U3.45 | length 239.5
  Bottom Layer w10: R32.2@1365,1247 1367,1245 1504.81,1245 1550.94,1291.13 U3.45@1550.94,1324.76
LED_0: J2.2 U2.35 | length 2501.1
  Top Layer w6: U2.35@2579.35,1309.35 U2.35@2588.89,1309.35
  Top Layer w8: 2458,1295 2555,1295 2569,1309 U2.35@2582,1309
  Top Layer w10: v1(2186,1639) 2169.87,1622.87 2169.87,1309.13 2206,1273 2436,1273 2458,1295 ; v1@3215,1776.09 J2.2@3848.21,1776.09
  Bottom Layer w10: v1(2186,1639) 2869,1639 3006,1776 v1(3209,1776)
LED_1: R1.1 R3.1 U2.6 | length 1955.8
  Top Layer w10: U2.6@2722.75,1254.24 2722.75,1266.61 2736.51,1280.37 2789.06,1280.37 2807.14,1262.28 2807.14,1230.86 2926.91,1111.09 2995,1111.09 v1(2995,1110) 3015,1110 3045,1140 R1.1@3045,1141.38
  Bottom Layer w10: v1(2995,1110) 2995,1425 3030,1460 3380,1460 3645,1725 3960,1725 4027,1792 R3.1@4040,1792
MDC: J14.3 U2.1 U3.16 | length 3182.2
  Top Layer w10: J14.3@862,2018 868,2024 1064,2024 1135,2095 1750,2095 ; v1(1750,2105) 1750,2095 ; 2069,2000 2134.13,1934.87 2134.13,1279.87 2179.13,1234.87 2485.16,1234.87 2493.29,1243 2614,1243 U2.1@2624,1253 ; 2069,2001 1975,2095 1750,2095
  Bottom Layer w10: U3.16@1550.94,1592.48 1550.94,1626.73 1580.83,1656.62 1642.84,1656.62 1750,1763.78 v1(1750,2105)
MDIO: J14.1 R45.1 U2.36 U3.17 | length 3530.6
  Top Layer w8: 2371,1254 2441,1254 2466,1279 2570.03,1279 2580.7,1289.67 U2.36@2588.89,1289.67
  Top Layer w10: J14.1@659,2021 662,2021 708,2067 1065,2067 1128,2130 1775,2130 ; v1(1775,2120) 1775,2130 ; 2086.87,2014.94 1971.81,2130 1775,2130 ; 2087,2015 2152,1950 2152,1295.91 2192.79,1255.13 2192.92,1255 2372,1255
  Bottom Layer w10: J14.1@661,2016 671,2006 695.56,2006 760,1941.56 R45.1@760,1937.62 ; U3.17@1570.63,1592.48 1570.63,1620.71 1588.67,1638.75 1654.21,1638.75 1775,1759.54 v1(1775,2120)
NetC1_2: C1.2 C2.1 R2.2 | length 80.8
  Top Layer w20: C2.1@2955.25,1408 2975.16,1408 ; C1.2@2975.16,1448.94 2975.16,1408 ; R2.2@2995.07,1408 2975.16,1408
NetC5_2: C5.2 C6.1 R13.1 | length 93.8
  Top Layer w20: C5.2@2951.12,1269 2975,1269 2975.56,1268.84 R13.1@2999.44,1268.84 ; C6.1@2975,1222.62 2975.56,1226.89 2976,1267.74 2976,1267.79 2976,1268
NetC7_1: C7.1 R14.1 R15.1 R18.2 | length 261.8
  Bottom Layer w25: C7.1@4114.86,1381.11 4111.63,1377.88 4034.99,1377.88 R14.1@4034.99,1297.69 4043.38,1289.3 R18.2@4131.95,1289.3
NetC9_1: C9.1 C26.1 C27.1 R17.1 U2.21 | length 51.2
  Top Layer w10: U2.21@2742.43,1482.58 2742.51,1482.66 2742.51,1495.03 2756.85,1509.37 2774.37,1509.37 v1(2775,1510)
NetC10_1: C10.1 C33.1 C34.1 R19.1 U2.9 | length 24.5
  Top Layer w10: U2.9@2781.8,1254.24 2781.8,1232.52 v1@2783.77,1230.55
  other v1: 2785,1230
NetC18_1: C18.1 C24.1 R96.1 U2.7 | length 286.2
  Top Layer w10: U2.7@2742.43,1247.42 2742.43,1216 2799.43,1159 2799.43,1150.57 C18.1@2806,1144 ; C18.1@2808,1142 2811,1139 2826,1139 C24.1@2860.3,1104.7 ; R96.1@2854.3,1017.7 2851.51,1020.49 2851.51,1089.49 2858.7,1096.67 2858.7,1101.3 C24.1@2858,1102
NetC28_1: C28.1 R23.1 R24.1 R25.2 | length 246.6
  Bottom Layer w25: C28.1@3825.2,496.09 3820.2,491.09 R23.1@3755.9,491.09 3756.4,491.59 R24.1@3756.4,576.09 3832.29,576.09 R25.2@3842.28,586.09
NetC30_1: C30.1 R28.1 Y1.3 | length 153.1
  Top Layer w10: R28.1@2487,1118.38 2487.5,1117.88 2487.5,1052.5 C30.1@2489,1051 ; R28.1@2490,1118 2490,1111.44 2493.81,1107.63 2566.24,1107.63 Y1.3@2566.6,1107.28
NetC31_1: C31.1 R26.1 R97.1 Y1.1 | length 348.4
  Top Layer w10: Y1.1@2641.4,1016.72 2641.4,1020.66 2680.37,1059.63 2710.63,1059.63 2716,1065 ; R97.1@2671.3,1168.3 2668.51,1165.51 2668.51,1155.88 2718,1106.39 2718,1067 2716,1065 ; R26.1@2735,948.62 2735,1013 2734,1014 2731.44,1014 2716,1029.44 2716,1065
NetC37_2: C37.2 J12.7 | length 69.8
  Bottom Layer w20: C37.2@1073.62,1185 1105,1185 1130,1210 J12.7@1133,1210.79
NetC38_2: C38.2 J12.1 | length 71.9
  Bottom Layer w10: J12.1@1029.17,1252.08 J12.1@1033.07,1255.98
  Bottom Layer w20: C38.2@968.62,1250 J12.1@1035,1250
NetC41_2: C41.2 J12.6 | length 64.4
  Bottom Layer w20: C41.2@968.62,1650 1030,1650 J12.6@1033,1650.16
NetC42_2: C42.2 J12.12 | length 74.7
  Bottom Layer w20: C42.2@1068.62,1715 1105,1715 1130,1690 J12.12@1133,1689.92
NetC43_1: C43.1 U3.15 Y2.1 | length 366.8
  Bottom Layer w10: U3.15@1531.26,1592.48 1531.26,1737.97 Y2.1@1603.27,1809.98 1580,1833.25 C43.1@1580,1919.81
NetC44_2: C44.2 R38.2 Y2.2 | length 248.5
  Bottom Layer w10: C44.2@1469.53,1919.81 1469.53,1833.72 Y2.2@1445.79,1809.98 1503.74,1752.03 R38.2@1503.74,1705.19
NetC74_2: C74.2 U4.54 | length 73.5
  Top Layer w10: U4.54@1864.21,506.77 1864.21,528.27 v1(1870.34,534.4)
  Bottom Layer w10: v1(1870.34,534.4) 1870.34,573.13 C74.2@1873.59,576.38
NetC75_2: C75.2 U4.17 | length 59.1
  Top Layer w8: U4.17@2061.06,853.23 2081.97,853.23 2085.74,857 v1(2090,857)
  Bottom Layer w20: C75.2@2063.15,861.3 2064.45,860 2067.45,857 v1(2090,857)
NetC76_1: C76.1 U4.55 | length 77.3
  Top Layer w10: U4.55@1883.9,506.77 1883.9,479.1 v1(1884.81,478.19)
  Bottom Layer w10: v1(1884.81,478.19) 1887,478.19 C76.1@1915.19,506.38 C76.1@1915.19,500.07
NetC82_1: C82.1 U6.1
NetC82_2: C82.2 D15.1 L9.1 U6.6
NetC88_1: C88.1 U8.1
NetC88_2: C88.2 D18.1 L10.1 U8.6
NetD2_2: D2.2 R3.2 | length 67.9
  Top Layer w10: v1(4137.66,1792.09) D2.2@4165.22,1792.09
  Bottom Layer w10: R3.2@4097.28,1792.09 v1(4137.66,1792.09)
NetD3_1: D3.1 J2.1 R5.1 | length 481.4
  Top Layer w10: J2.1@3848.21,1676.09 3858.12,1686 D3.1@4163.22,1686
  Bottom Layer w10: J2.1@3848.21,1676.09 3858.12,1686 R5.1@4006.38,1686
NetD3_2: D3.2 R7.1 | length 86.9
  Top Layer w10: D3.2@4209,1686 v1(4252,1686) v1@4252.47,1686
  Bottom Layer w10: R7.1@4208.52,1686 v1(4252,1686)
NetD4_1: D4.1 R12.1 | length 85
  Top Layer w10: D4.1@4208.53,1892.09 v1(4252,1892.09)
  Bottom Layer w10: R12.1@4210.49,1892.09 v1(4252,1892.09)
NetD4_2: D4.2 J2.3 R16.1 | length 406.2
  Top Layer w10: J2.3@3848.21,1876.09 3864.12,1892 D4.2@4163.22,1892
  Bottom Layer w10: R16.1@3763.62,1876.09 J2.3@3848.21,1876.09
NetD8_1: D8.1 R40.1 | length 70
  Top Layer w10: v1(2220,92.56) D8.1@2258.03,92.56
  Bottom Layer w10: v1(2220,92.56) 2232.44,92.56 R40.1@2246.24,106.36
NetD8_2: D8.2 R39.1 | length 63.4
  Top Layer w10: D8.2@2285.59,92.56 v1(2321.65,92.56)
  Bottom Layer w10: R39.1@2300,106.36 2313.8,92.56 v1(2321.65,92.56)
NetD9_1: D9.1 R42.1 | length 57.2
  Top Layer w10: v1(2354.74,92.56) D9.1@2385.19,92.56
  Bottom Layer w10: v1(2354.74,92.56) 2357.3,90 R42.1@2373.68,106.38
NetD9_2: D9.2 R41.1 | length 62.8
  Top Layer w10: D9.2@2412.75,92.56 v1(2448.18,92.56)
  Bottom Layer w10: R41.1@2426.53,106.38 2440.35,92.56 v1(2448.18,92.56)
NetD10_1: D10.1 R44.1 | length 64.9
  Top Layer w10: v1(2479.12,92.56) 2480,91.68 D10.1@2515.59,91.68
  Bottom Layer w10: v1(2479.12,92.56) 2488.89,92.56 R44.1@2501.81,105.48
NetD10_2: D10.2 R43.1 | length 64.5
  Top Layer w10: D10.2@2543.15,91.68 v1(2580.4,91.68)
  Bottom Layer w10: R43.1@2558.89,105.5 2572.71,91.68 v1(2580.4,91.68)
NetD11_2: D11.2 J9.1 | length 432.7
  Top Layer w10: J9.1@1663,365 1766,365 1864,267 v1(1977,267)
  Bottom Layer w10: v1(1977,267) 2041,267 D11.2@2051,277
NetD12_1: D12.1 J19.1 R56.1 R58.1 U5.4 | length 1803.6
  Top Layer w10: D12.1@1082.99,710 D12.1@1080,712.99 1099,694 v1(1180,694)
  Bottom Layer w10: 1180,710 1180,695 1205,670 1285,670 1285,634.24 1314.11,605.13 1373.58,605.13 1374.71,604 1423.29,604 1423.42,604.13 1659.16,604.13 1659.42,603.87 1738.87,603.87 1815,680 1960,680 1975,695 2111.71,695 2163.09,746.38 2412.38,746.38 2430,764 J19.1@2490,764 ; 1180,715 1180,865 ; R56.1@1180,906.38 1180,865 ; R58.1@1230,865 1180,865
NetD12_2: D12.2 R55.1 | length 168.9
  Top Layer w10: D12.2@1080,775 1100,795 v1(1205,795)
  Bottom Layer w10: v1(1205,795) 1200,795 1201.38,793.62 R55.1@1230,793.62
NetD13_1: D13.1 R65.2 | length 133.5
  Top Layer w10: D13.1@1440,1105 D13.1@1441.65,1105 v3(1470,1105)
  Bottom Layer w10: v3(1470,1105) 1525,1105 1540,1090 1540,1065 R65.2@1542.24,1065
NetD14_1: D14.1 R66.2 | length 94.8
  Top Layer w10: D14.1@1920,2050 D14.1@1921.65,2050 v1(1950,2050)
  Bottom Layer w10: R66.2@1926.38,2105 1926.38,2073.62 v1(1950,2050)
NetD16_2: D16.2 R67.2 | length 49.4
  Top Layer w10: D16.2@385,338.44 R67.2@385,383.88 R67.2@385,387.79
NetD17_2: D17.2 R69.2 | length 64.6
  Top Layer w10: v1@1181.77,2016.77 v1(1181.77,2018.23) D17.2@1181.77,2048.82
  Bottom Layer w10: R69.2@1179.8,2048.82 1181.77,2048.82 v1(1181.77,2018.23)
NetD19_2: D19.2 R72.2 | length 83.3
  Top Layer w10: R72.2@3265,180 D19.2@3265,263.35
NetD20_2: D20.2 F1.1 | length 133.4
  Bottom Layer w50: F1.1@440,777.09 440,908.74 D20.2@441.26,910
NetD21_2: D21.2 R73.2 | length 224.7
  Top Layer w10: D21.2@141.65,946.46 R73.2@366.38,946.46
NetD22_1: D22.1 R99.1 | length 61
  Top Layer w10: v1(2611.34,91.68) 2611.77,92.12 2641.12,92.12 D22.1@2642,93
  Bottom Layer w10: v1(2611.34,91.68) 2613.64,91.68 2617.56,95.61 2627.61,95.61 R99.1@2636,104
NetD22_2: D22.2 R27.1 | length 69.3
  Top Layer w10: D22.2@2672,92 2672.12,92.12 2712.17,92.12 v1(2712.61,91.68)
  Bottom Layer w10: R27.1@2691,105 2691,102.68 2698.07,95.61 2700.39,95.61 2702.69,93.31 2710.98,93.31 v1(2712.61,91.68)
NetF1_2: F1.2 J22.1 TP8.1 | length 572.6
  Top Layer w50: J22.1@548.35,660 600,660 700,560 TP8.1@970,560
  Bottom Layer w50: F1.2@440,662.91 545.43,662.91 J22.1@548.35,660
NetJ3_1: J3.1 R20.1 | length 76.4
  Bottom Layer w10: R20.1@3150,973.62 J3.1@3150,1050
NetJ7_1: J7.1 R26.2 | length 151.6
  Top Layer w10: R26.2@2735,892 J7.1@2735.17,740.38
NetJ8_1: J8.1 R31.2 | length 900.3
  Bottom Layer w10: R31.2@2907,1565 2909,1563 2967,1563 3005.01,1524.99 3224.99,1524.99 3489.57,1789.57 J8.1@3489.57,1981.09
NetJ12_14: J12.14 R32.1 | length 104.1
  Bottom Layer w10: J12.14@1234,1308 1246.44,1308 1308.44,1246 R32.1@1312.38,1246
NetJ12_16: J12.16 R34.2 | length 159.1
  Bottom Layer w10: J12.16@1233.12,1690 J12.16@1233,1690.12 1233,1755 1279,1801 R34.2@1305,1801 ; J12.16@1239,1713 J12.16@1242,1713
NetJ16_1: J16.1 R47.2 | length 1843.1
  VCC2 w10: J16.1@659,1913 664,1913 686.48,1890.52 686.48,1885.52 806,1766 806,1143 1071,878 1575,878 1612,841 v3(1612,816)
  Bottom Layer w10: R47.2@1611,763.62 1611.5,764.12 1611.5,814.5 v3@1613,816
NetJ17_1: J17.1 R46.2 | length 1771.2
  VCC2 w10: J17.1@859,1918 859,1171 1097,933 1580,933 1664,849 v1@1664,815
  Bottom Layer w10: v1@1663,815 v1(1664,814) R46.2@1664,763.62
NetQ1_1: Q1.1 R61.1 | length 91.3
  Bottom Layer w10: Q1.1@1432.4,967.76 1462.24,967.76 1480,950 R61.1@1516.38,950
NetQ1_3: Q1.3 R65.1 | length 102.8
  Bottom Layer w10: Q1.3@1395,1062.24 1395,1065 R65.1@1495,1065
NetQ2_1: Q2.1 R62.1 | length 62.7
  Bottom Layer w10: R62.1@2108.62,1950 2110,1950 2116.17,1956.17 Q2.1@2116.17,2008.8
NetQ2_3: Q2.3 R66.1 | length 105.5
  Bottom Layer w10: R66.1@1973.62,2105 2075,2105 Q2.3@2078.77,2103.29
NetR29_1: R29.1 R30.1 U2.14 | length 317.4
  Top Layer w10: U2.14@2813,1368 2845,1368 2877,1400 2877,1423.39 2947,1493.39 2947,1559.62 R30.1@2948.38,1561 ; R30.1@2948.38,1561.38 R29.1@2948.38,1611
NetR36_1: R36.1 U3.12 | length 81.6
  Bottom Layer w10: R36.1@1395,1591.81 1397.06,1589.75 1430.78,1589.75 1453.65,1566.89 U3.12@1466.3,1566.89
NetR37_2: R37.2 U3.44 | length 99
  Bottom Layer w10: R37.2@1554,1232.62 1554,1262 1570.63,1278.63 U3.44@1570.63,1324.76
NetR38_1: R38.1 U3.14 | length 68.7
  Bottom Layer w10: R38.1@1503.74,1657.94 1511.57,1650.11 U3.14@1511.57,1592.48
NetR46_1: R46.1 U4.42 | length 124.6
  Top Layer w10: v1(1665,677) 1692,650 U4.42@1741,650
  Bottom Layer w10: v1(1665,677) 1664.5,677.5 1664.5,713.5 R46.1@1665,714
NetR47_1: R47.1 U4.43 | length 175.8
  Top Layer w10: v1(1612,678) 1659.21,630.79 U4.43@1733.39,630.79
  Bottom Layer w10: v1(1612,678) 1611.5,678.5 1611.5,710.5 R47.1@1613,712
NetR52_1: R52.1 U4.51 | length 64.1
  Top Layer w10: U4.51@1805.16,506.77 1805.16,532.82 v1(1805.44,532.82)
  Bottom Layer w10: R52.1@1789.2,501.81 1805.44,518.05 v1(1805.44,532.82)
NetR57_2: R57.2 R59.2 U5.1 | length 205.1
  Bottom Layer w10: R57.2@1340.92,857.09 1367.2,857.09 1395.21,829.08 U5.1@1395.21,744.49 1441.08,744.49 R59.2@1447.3,750.71
NetR60_1: R60.1 R63.2 U6.3
NetR64_2: R64.2 R68.2 U7.8 | length 95.3
  Top Layer w10: U7.8@1730.12,1045 R64.2@1778,1045 ; R68.2@1780,999 R64.2@1780,1046.38
NetR70_1: R70.1 R71.2 U8.3
NetR96_2: R96.2 U10.6 | length 64.4
  Top Layer w10: R96.2@2888,987 2892.18,987 2904.59,999.41 2946.41,999.41 U10.6@2947,1000
NetR98_1: R98.1 U10.1 U10.2 | length 127.2
  Top Layer w10: U10.1@3025.39,999.41 3026.09,999.41 3027,1000.31 U10.2@3027,1024 ; U10.1@3026,999 3026.41,999.41 3053.21,999.41 3093.25,959.37 3097.19,959.37 3104,952.56 R98.1@3104,948.62
NetR103_1: R103.1 U2.18 | length 120.2
  Top Layer w10: U2.18@2817.49,1446.57 2824.22,1446.57 2863,1485.35 2863,1531 2864.19,1532.19 2864.19,1532.63 2871.56,1540 R103.1@2872,1540
NetR104_1: R104.1 U2.17 | length 161.3
  Top Layer w10: U2.17@2817.49,1426.88 2817.57,1426.96 2829.94,1426.96 2880.87,1477.9 2880.87,1507 2901.87,1528 2902,1528 2903.19,1529.19 2903.19,1537.19 R104.1@2909,1543
NetS2_1: S2.1 U5.3 | length 229.1
  Top Layer w10: v1(1357.7,668.17) 1357.7,731.62 1374.98,748.9 S2.1@1477.95,748.9
  Bottom Layer w10: v1@1357.62,668.09 v1(1357.7,668.17) 1359.21,669.69 U5.3@1395.21,669.69
NetTP1_1: TP1.1 U4.44 | length 137
  Top Layer w10: v1@1655.96,581.74 1685.2,608.13 1688.5,611.1 U4.44@1740.2,611.1
  Bottom Layer w10: TP1.1@1615,565 1619.5,566.5 1636,572 1643,572 1643,572.7 1651,580.7 v1@1651,581
  other v1: 1650,582
NetTP2_1: TP2.1 U4.45 | length 194.3
  Top Layer w10: v1(1650,484) 1673,507 1673,552.27 1712.15,591.42 U4.45@1740.2,591.42
  Bottom Layer w10: TP2.1@1619,489 1622.37,485.63 1648.37,485.63 v1(1650,484)
NetTP3_1: TP3.1 U4.31 | length 61.7
  Top Layer w10: v1(1780,825) 1785.47,830.47 U4.31@1785.47,853.23
  Bottom Layer w10: TP3.1@1765,800 1780,815 v1(1780,825)
NetTP4_1: TP4.1 U4.30 | length 75.6
  Top Layer w10: U4.30@1805.16,853.23 1805.16,829.84 v1(1815,820)
  Bottom Layer w10: v1(1815,820) 1835,800 TP4.1@1845,800
NetTP5_1: TP5.1 U4.29 | length 93.9
  Top Layer w10: U4.29@1824.84,853.23 1824.84,879.84 v1(1825,880)
  Bottom Layer w10: v1(1825,880) 1885,880 TP5.1@1890,875
NetTP6_1: TP6.1 U4.28 | length 128.8
  Top Layer w10: U4.28@1844.53,853.23 1844.53,825.47 1850,820 v1(1890,820)
  Bottom Layer w10: v1(1890,820) 1915,820 TP6.1@1935,800
NetTP7_1: TP7.1 U4.46 | length 230.6
  Top Layer w10: v1(1700,523) 1711,534 1711,561 1721.73,571.73 U4.46@1740.2,571.73
  Bottom Layer w10: TP7.1@1546,522 1605.95,522 1606.51,522.56 1699.56,522.56 v1(1700,523)
NetU4_57: U4.57 Y3.1 | length 127.6
  Top Layer w10: Y3.1@1873.85,399.67 1873.85,415.21 1923.27,464.63 U4.57@1923.27,506.77
NetU4_58: U4.58 Y3.3 | length 127.4
  Top Layer w10: U4.58@1942.95,506.77 1942.95,463.65 1991.96,414.65 Y3.3@1991.96,399.67
P1.0: R40.2 U4.18 | length 870.2
  Top Layer w10: U4.18@2041.38,853.23 2041.38,867.12 2055.99,881.73 2102.4,881.73 2248.02,736.11 v1(2248.02,187.87)
  Bottom Layer w10: R40.2@2246.24,153.6 2248.02,155.38 v1(2248.02,187.87)
P1.1: R39.2 U4.19 | length 944.7
  Top Layer w10: U4.19@2021.69,853.23 2021.69,874.65 2046.65,899.61 2109.8,899.61 2265.89,743.51 2265.89,292.3 2300,258.19 v1(2300,186.06)
  Bottom Layer w10: R39.2@2300,153.6 v1(2300,186.06)
P1.2: R42.2 U4.20 | length 1027.7
  Top Layer w10: U4.20@2002.01,853.23 2002.01,880.24 2039.25,917.48 2117.21,917.48 2283.77,750.92 2283.77,303.69 2373.68,213.77 v1(2373.68,186.06)
  Bottom Layer w10: R42.2@2373.68,153.62 v1(2373.68,186.06)
P1.3: R41.2 U4.21 | length 1102.2
  Top Layer w10: U4.21@1982.32,853.23 1982.32,885.83 2031.85,935.35 2124.61,935.35 2301.64,758.32 2301.64,313.96 v1(2426.53,189.08)
  Bottom Layer w10: R41.2@2426.53,153.62 v1(2426.53,189.08)
P1.4: R44.2 U4.22 | length 1214.4
  Top Layer w10: U4.22@1962.64,853.23 1962.64,891.42 2024.44,953.23 2132.01,953.23 2319.52,765.73 2319.52,321.37 2380.1,260.79 2427.09,260.79 v1(2500,187.87)
  Bottom Layer w10: v1(2500,187.87) 2501.81,186.06 R44.2@2501.81,152.73
P1.5: R43.2 U4.23 | length 1311
  Top Layer w10: U4.23@1942.95,853.23 1942.95,897.02 2017.04,971.1 2139.42,971.1 2337.39,773.13 2337.39,328.77 2386.16,280 2467.97,280 v1(2557.97,190)
  Bottom Layer w10: v1(2557.97,190) 2558.89,189.08 R43.2@2558.89,152.75
P1.6: R99.2 U4.24 | length 1416.3
  Top Layer w10: U4.24@1923.27,860.04 1923.27,901.27 1924,902 1924,903.34 2009.63,988.98 2149.02,988.98 2357,781 2357,338 2389,306 2487.85,306 2604.85,189 v1(2635,189)
  Bottom Layer w10: R99.2@2635,154 2634.59,154.41 2634.59,188.59 v1(2635,189)
P1.7: R27.2 U4.25 | length 1512.1
  Top Layer w10: U4.25@1903.58,853.23 1903.58,908.2 2002.23,1006.85 2156.43,1006.85 2374.87,788.4 2374.87,345.4 2396.4,323.87 2495.25,323.87 2600.13,219 2657,219 v1(2685,191)
  Bottom Layer w10: v1(2685,191) 2686.63,189.37 2686.63,161.37 R27.2@2691.63,156.37
"Rev. sel. 0": R86.1 R90.1 U4.1 | length 583.7
  Top Layer w10: U4.1@2086.65,532.36 2115.64,532.36 2121,527 v1(2122,527) ; v1(2450,389) 2495,389 R90.1@2496,388
  Bottom Layer w10: v1(2122,527) 2122,425 2159,388 2236,388 2245.13,397.13 2422.87,397.13 2431,389 v1(2450,389) 2451.5,387.5 2494.5,387.5 R86.1@2496,386
"Rev. sel. 1": R87.1 R91.1 U4.2 | length 512.5
  Top Layer w10: U4.2@2086.65,552.05 v1@2123,552.05 ; v1(2450,446) 2495,446 R91.1@2496,445
  Bottom Layer w10: v1@2125.42,555 2144.13,536.29 2144.13,516.87 2166,495 2401,495 v1(2450,446) 2451.5,444.5 2495.88,444.5 R87.1@2497.38,443
  other v1: 2124,556
"Rev. sel. 2": R88.1 R92.1 U4.3 | length 505.8
  Top Layer w10: U4.3@2086.65,571.73 2108.44,571.73 2117.92,581.21 v1@2123.49,582.62 ; v1@2122.87,582 v1@2123.49,582.62 ; v1(2124,583) 2123.87,583 v1@2123.49,582.62 ; v1@2125,583 2124.06,582.76 v1@2123.49,582.62 ; v1(2450,504) R92.1@2496.38,504
  Bottom Layer w10: v1@2123,582 2144,582 2153,591 2269,591 2301,559 2395,559 v1(2450,504) 2451.5,502.5 2495.88,502.5 R88.1@2497.38,501
"Rev. sel. 3": R89.1 R93.1 U4.4 | length 801.2
  Top Layer w10: U4.4@2096.13,591.42 U4.4@2086.65,591.42 2086.65,591 2100.13,591 2119.13,610 v1(2124,610) ; v1(2450,562) 2451,561 R93.1@2496,561
  Bottom Layer w10: v1(2124,610) 2124,643.65 2189.7,709.35 2508.79,709.35 2535.35,682.79 2535.35,645.21 2496.14,606 2468,606 2450,588 v1(2450,562) 2451.63,560.37 2492.63,560.37 R89.1@2493,560
SBWTCK: J15.2 U4.59 | length 300.5
  Top Layer w10: U4.59@1962.64,506.77 1962.64,485.55 1968.19,480 2138,480 J15.2@2188.37,532.93 ; J15.2@2188.37,530.37 J15.2@2188.37,532.93 ; J15.2@2188.37,546.38 J15.2@2188.37,532.93 ; J15.2@2197,542 J15.2@2188.37,532.93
